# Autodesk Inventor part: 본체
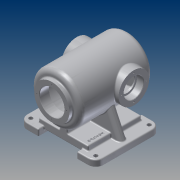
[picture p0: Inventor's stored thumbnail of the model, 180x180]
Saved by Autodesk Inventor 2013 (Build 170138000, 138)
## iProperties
Created: 2013-06
Part Number: 본체
Document SubType Name: Modeling
Designer: SeoGD™[esajin.kr]
Density: 2.71 g/cm^3
Material: 알루미늄 6061
Mass: 4578.67 g
Surface Area: 2686.6 cm^2
Volume: 1689.54 cm^3
Author: SeoGD™[esajin.kr]
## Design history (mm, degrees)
sketch "스케치1"
  geometry: L1 (-100, 85)-(-50, 85); L2 (-50, 85)-(-50, -85); L3 (-50, -85)-(-100, -85); L4 (-100, -85)-(-100, 85); L5 (50, 85)-(100, 85); L6 (100, 85)-(100, -85); L7 (100, -85)-(50, -85); L8 (50, -85)-(50, 85); 3 further points
  constraints: 16 end point, 4 parallel, 2 equal length, 2 horizontal, 2 horizontal alignment, 2 midpoint, 2 perpendicular
  dimensions: "d0" = 100 distance between parallel lines of L8 L2; "d1" = 170 distance of L3.end L1.start; "d3" = 200 distance between parallel lines of L6 L4; "d4" = 50 distance from line of point (0, 0) L2 (= 0.5 x d0)
extrude "돌출1" new body sketch "스케치1" distance "d5" = 16; taper "d6" = 0 deg
node "작업 평면1"
sketch "스케치2"
  geometry: L1 (-65, 70)-(65, 70); L2 (65, 70)-(65, -70); L3 (65, -70)-(-65, -70); L4 (-65, -70)-(-65, 70); 3 further points
  constraints: 8 end point, 2 midpoint, 2 parallel, 1 horizontal, 1 horizontal alignment, 1 perpendicular, 1 vertical alignment
  dimensions: "d8" = 130 distance of L2.end L3.end; "d9" = 140 distance of L1.end L2.end
extrude "돌출2" join sketch "스케치2" distance "d10" = 20; taper "d11" = 0 deg
sketch "스케치3"
  geometry: L1 (-100, 110)-(100, 110); L2 (85, 0)-(-85, 0) reference; L3 (100, 110)-(100, 175); L4 (100, 175)-(-90, 175); L5 (-90, 175)-(-90, 156); L6 (-90, 156)-(-100, 156); L7 (-100, 156)-(-100, 110); L8 (90, 110)-(90, 165); L9 (90, 165)-(-75, 165); L10 (-75, 165)-(-75, 110); L11 (-100, 142.5)-(-75, 142.5); 3 further points
  constraints: 20 end point, 5 perpendicular, 4 parallel, 4 point on line, 2 midpoint, 1 horizontal, 1 vertical alignment
  dimensions: "d12" = 110 distance from line of L2 L1.end; "d13" = 200 distance of L1.start L1.end; "d14" = 130 diameter of L4 L1; "d15" = 92 diameter of L6 L1; "d16" = 10 distance of L5.end L6.end; "d42" = 110 diameter of L9 L1; "d43" = 10 distance between parallel lines of L3 L8; "d44" = 25 distance between parallel lines of L10 L7; "d45" = 65 diameter of L11 L1
revolve "회전1" sketch "스케치3" stored, may be unused: angle "d17" = 90 deg
sketch "스케치4"
  geometry: L1 (-50, 70)-(50, 70) reference; L2 (50, -70)-(-50, -70) reference; L3 (-10, 70)-(-10, -70); L4 (10, -70)-(10, 70); 1 further point
  constraints: 4 end point, 4 point on line, 2 perpendicular
  dimensions: "d18" = 20 distance between parallel lines of L4 L3; "d19" = 10 distance from line of point (0, 0) L3
extrude "돌출3" join sketch "스케치4" stored distance "d20" = 10; taper "d21" = 0 deg
node "작업 평면2"
sketch "스케치5"
  geometry: L1 (-50, -8)-(0, -8) reference; L2 (100, -8)-(150, -8) reference; L3 (-40, -8)-(-8.943, -74.601); L4 (140, -8)-(108.943, -74.601); L5 (-50, 8)-(-50, -8) reference; L6 (150, 8)-(150, -8) reference; A1 r 65 centre (50, -102) between (-8.943, -74.601) and (108.943, -74.601) reference; 1 further point
  constraints: 4 end point, 2 point on circle, 2 point on line, 1 equal length
  dimensions: "d23" = 10 distance from line of L3.start L5; "d24" = 10 distance from line of L4.start L6; "d25" = 25 deg angle of L3 L5
feature "리브1" sketch "스케치5" dims "d26" = 1, "d27" = 20, "d28" = 0
node "작업 평면3"
sketch "스케치6"
  geometry: L1 (100, 156)-(100, 64) reference; C1 r 40 at (-40, 110); 2 further points
  constraints: 1 centre point, 1 horizontal alignment, 1 midpoint
  dimensions: "d37" = 80 diameter of C1; "d38" = 140 distance from line of C1.centre L1
extrude "돌출4" join sketch "스케치6" stored distance "d39" = 10; taper "d40" = 0 deg
hole "구멍1" diameter "d48" = 42; stored, may be unused: countersink angle "d52" = 90 deg, drill point angle "d54" = 118 deg; dims "d46" = 10, "d47" = 10, "d49" = 6, "d50" = 52, "d51" = 18, "d53" = 8
sketch "스케치7"
  geometry: C1 r 40 at (0, 0) reference; 2 further points
  constraints: 1 horizontal alignment
  dimensions: "d55" = 32.5 distance of point (32.5, 0) C1.centre
hole "구멍2" sketch "스케치7" at (32.5, 0) diameter "d56" = 3.242; stored, may be unused: countersink angle "d60" = 90 deg, drill point angle "d62" = 118 deg; dims "d57" = 10, "d58" = 52, "d59" = 18, "d61" = 13
sketch "스케치8"
  geometry: C1 r 46 at (0, 0) reference; 2 further points
  constraints: 1 vertical alignment
  dimensions: "d66" = 39 distance of C1.centre point (0, 39)
hole "구멍3" sketch "스케치8" at (0, 39) diameter "d67" = 3.242; stored, may be unused: countersink angle "d71" = 90 deg, drill point angle "d73" = 118 deg; dims "d68" = 10, "d69" = 52, "d70" = 18, "d72" = 13
fillet "모깎기7" dims "d77" = 20, "d78" = 13, "d79" = 3, "d80" = 10
fillet "모깎기8" dims "d81" = 3
fillet "모깎기9" dims "d82" = 3
fillet "모깎기10" dims "d83" = 3, "d84" = 0.3
chamfer "모따기1" distance "d85" = 1; stored, may be unused: second distance "d86" = 2, angle "d87" = 45 deg
node "작업 평면4"
sketch "스케치10"
  geometry: 5 further points
  constraints: 2 horizontal alignment, 2 vertical alignment
  dimensions: "d90" = 170 distance of point (85, 70) point (-85, 70); "d91" = 140 distance of point (-85, 70) point (-85, -70); "d92" = 70 vertical distance of point (0, 0) point (-85, -70) (= 0.5 x d91); "d93" = 85 horizontal distance of point (0, 0) point (-85, 70) (= 0.5 x d90)
hole "구멍4" sketch "스케치10" at (-85, 70), (85, 70), (85, -70), (-85, -70) diameter "d94" = 10; stored, may be unused: countersink angle "d98" = 90 deg, drill point angle "d100" = 118 deg; dims "d95" = 6, "d96" = 4, "d97" = 2, "d99" = 8
sketch "스케치11"
  geometry: L1 (13, -70)-(62, -70) reference; L2 (65, -67)-(65, -13) reference; 2 further points
  constraints: 1 other
  dimensions: "d101" = 30 distance from line of point (55, -40) L1; "d102" = 10 distance from line of point (55, -40) L2
feature "엠보싱2" sketch "스케치11" dims "d0" = 100, "d1" = 170, "d3" = 200, "d4" = 50 (= 0.5 x d0), "d103" = 1, "d104" = 0
node "솔리드1"
mirror "대칭1"
pattern_circular "원형 패턴1" dims angle "d64" = 360 deg
mirror "대칭3"
pattern_circular "원형 패턴2" dims angle "d75" = 360 deg
other parameters: "d7" = 8, "d36" = -75
